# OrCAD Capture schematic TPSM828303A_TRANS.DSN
size D; title: TPSM828303A; rev: 1.0; note: Datasheet: <SLVSGM1B> EVM: <SLVUCQ8, SLVUCX6>; note: Synchronous Step Down Converter
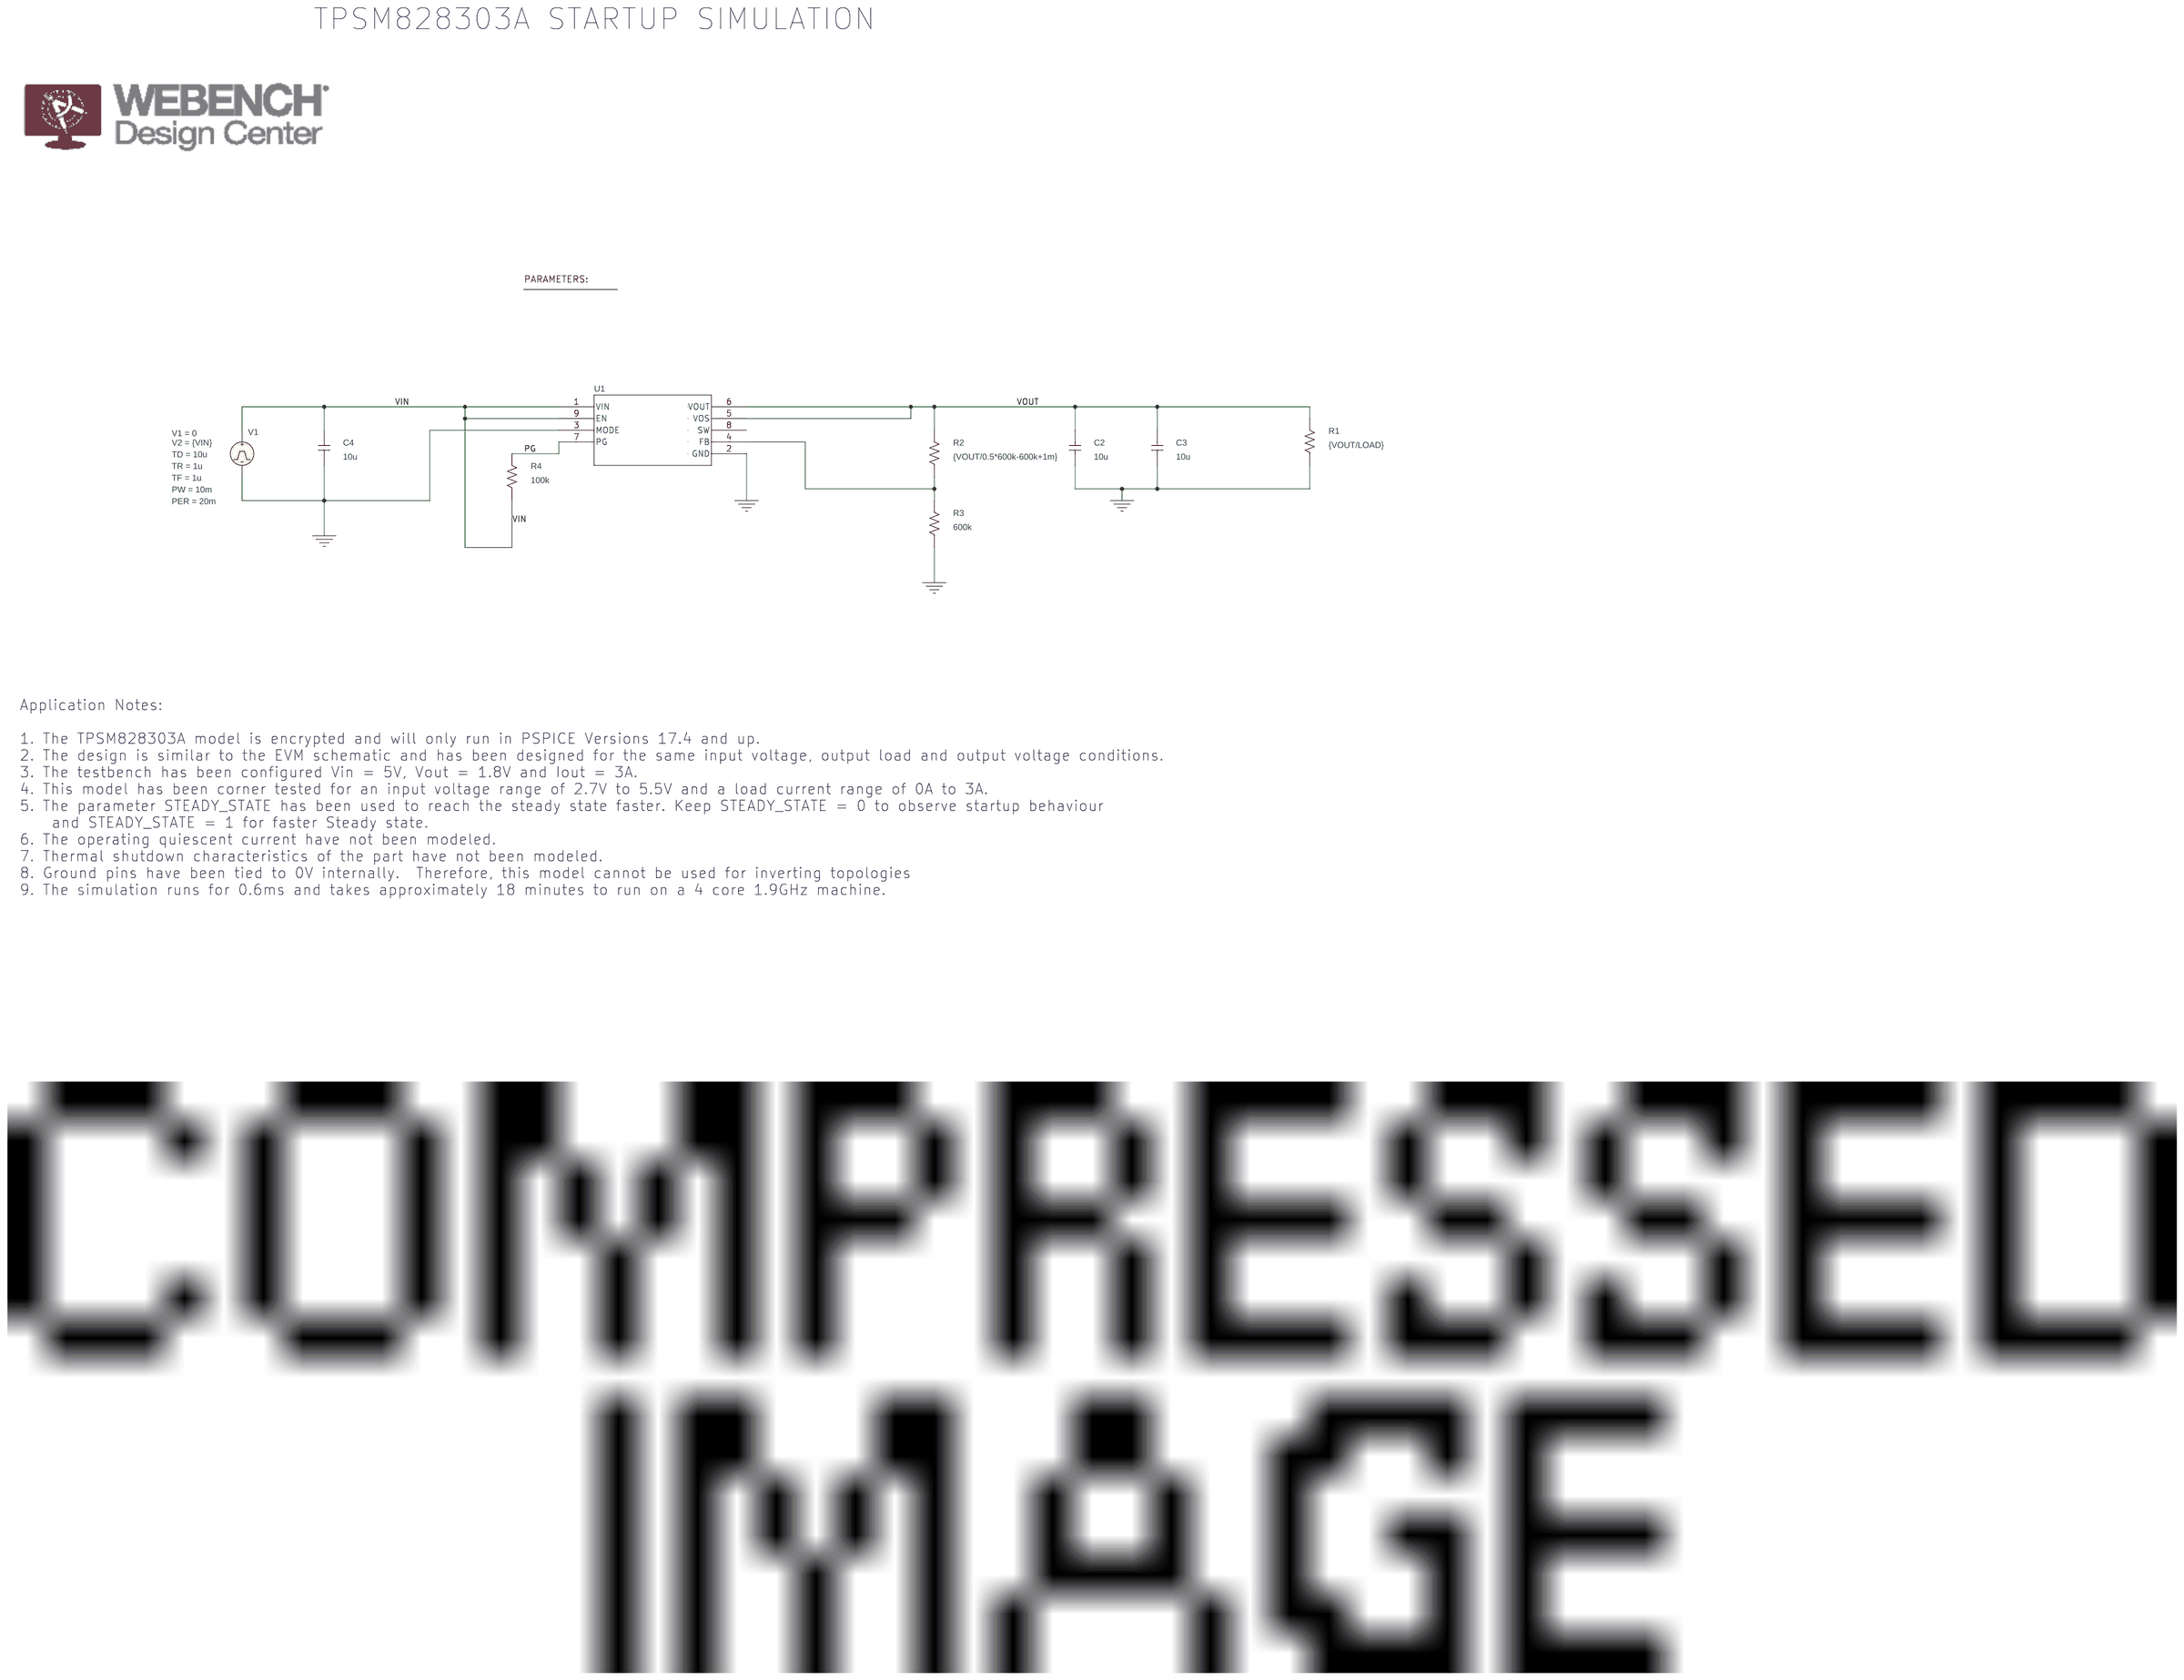
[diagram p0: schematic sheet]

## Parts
1  PARAM
C2  10u  [cap196]
C3  10u  [cap196]
C4  10u  [cap196]
R1  {VOUT/LOAD}  [AXRC05]
R2  {VOUT/0.5*600k-600k+1m}  [AXRC05]
R3  600k  [AXRC05]
R4  100k  [AXRC05]
U1  Value  [RDS0009A-MFG]
V1  VPULSE

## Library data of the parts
1 = PARAM: DCR: 22m; LOAD: 3; STEADY_STATE: 0; VIN: 5; VOUT: 1.8
C2-C4 = C
R1-R4 = R
U1 = TPSM828303ARDS_TRANS
V1 = VPULSE: PER: 20m; PW: 10m; TD: 10u; TF: 1u; TR: 1u; V1: 0; V2: {VIN}

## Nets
VIN: C4.2 R4.1 U1.1(VIN) U1.9(EN) V1.1(+)
0: C2.1 C3.1 C4.1 R1.1 R3.1 U1.2(GND) U1.3(MODE) V1.2(-)
PG: R4.2 U1.7(PG)
VOUT: C2.2 C3.2 R1.2 R2.2 U1.5(VOS) U1.6(VOUT)
N16774150: R2.1 R3.2 U1.4(FB)

Not connected (* = marked no-connect by the designer): U1 8(SW)

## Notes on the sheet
- TPSM828303A STARTUP SIMULATION
- Application Notes:
  1. The TPSM828303A model is encrypted and will only run in PSPICE Versions 17.4 and up.
  2. The design is similar to the EVM schematic and has been designed for the same input voltage, output load and output voltage conditions.
  3. The testbench has been configured Vin = 5V, Vout = 1.8V and Iout = 3A.
  4. This model has been corner tested for an input voltage range of 2.7V to 5.5V and a load current range of 0A to 3A.
  5. The parameter STEADY_STATE has been used to reach the steady state faster. Keep STEADY_STATE = 0 to observe startup behaviour
      and STEADY_STATE = 1 for faster Steady state.
  6. The operating quiescent current have not been modeled.
  7. Thermal shutdown characteristics of the part have not been modeled.
  8. Ground pins have been tied to 0V internally.  Therefore, this model cannot be used for inverting topologies
  9. The simulation runs for 0.6ms and takes approximately 18 minutes to run on a 4 core 1.9GHz machine.
